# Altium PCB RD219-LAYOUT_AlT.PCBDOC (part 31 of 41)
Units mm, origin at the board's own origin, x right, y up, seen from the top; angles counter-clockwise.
Board outline 209.75 x 159.97 mm, 2 copper layers (TOP, BOTTOM), stack 0 mm thick; 398 components, 199 nets, 1469 pads, 0 vias.
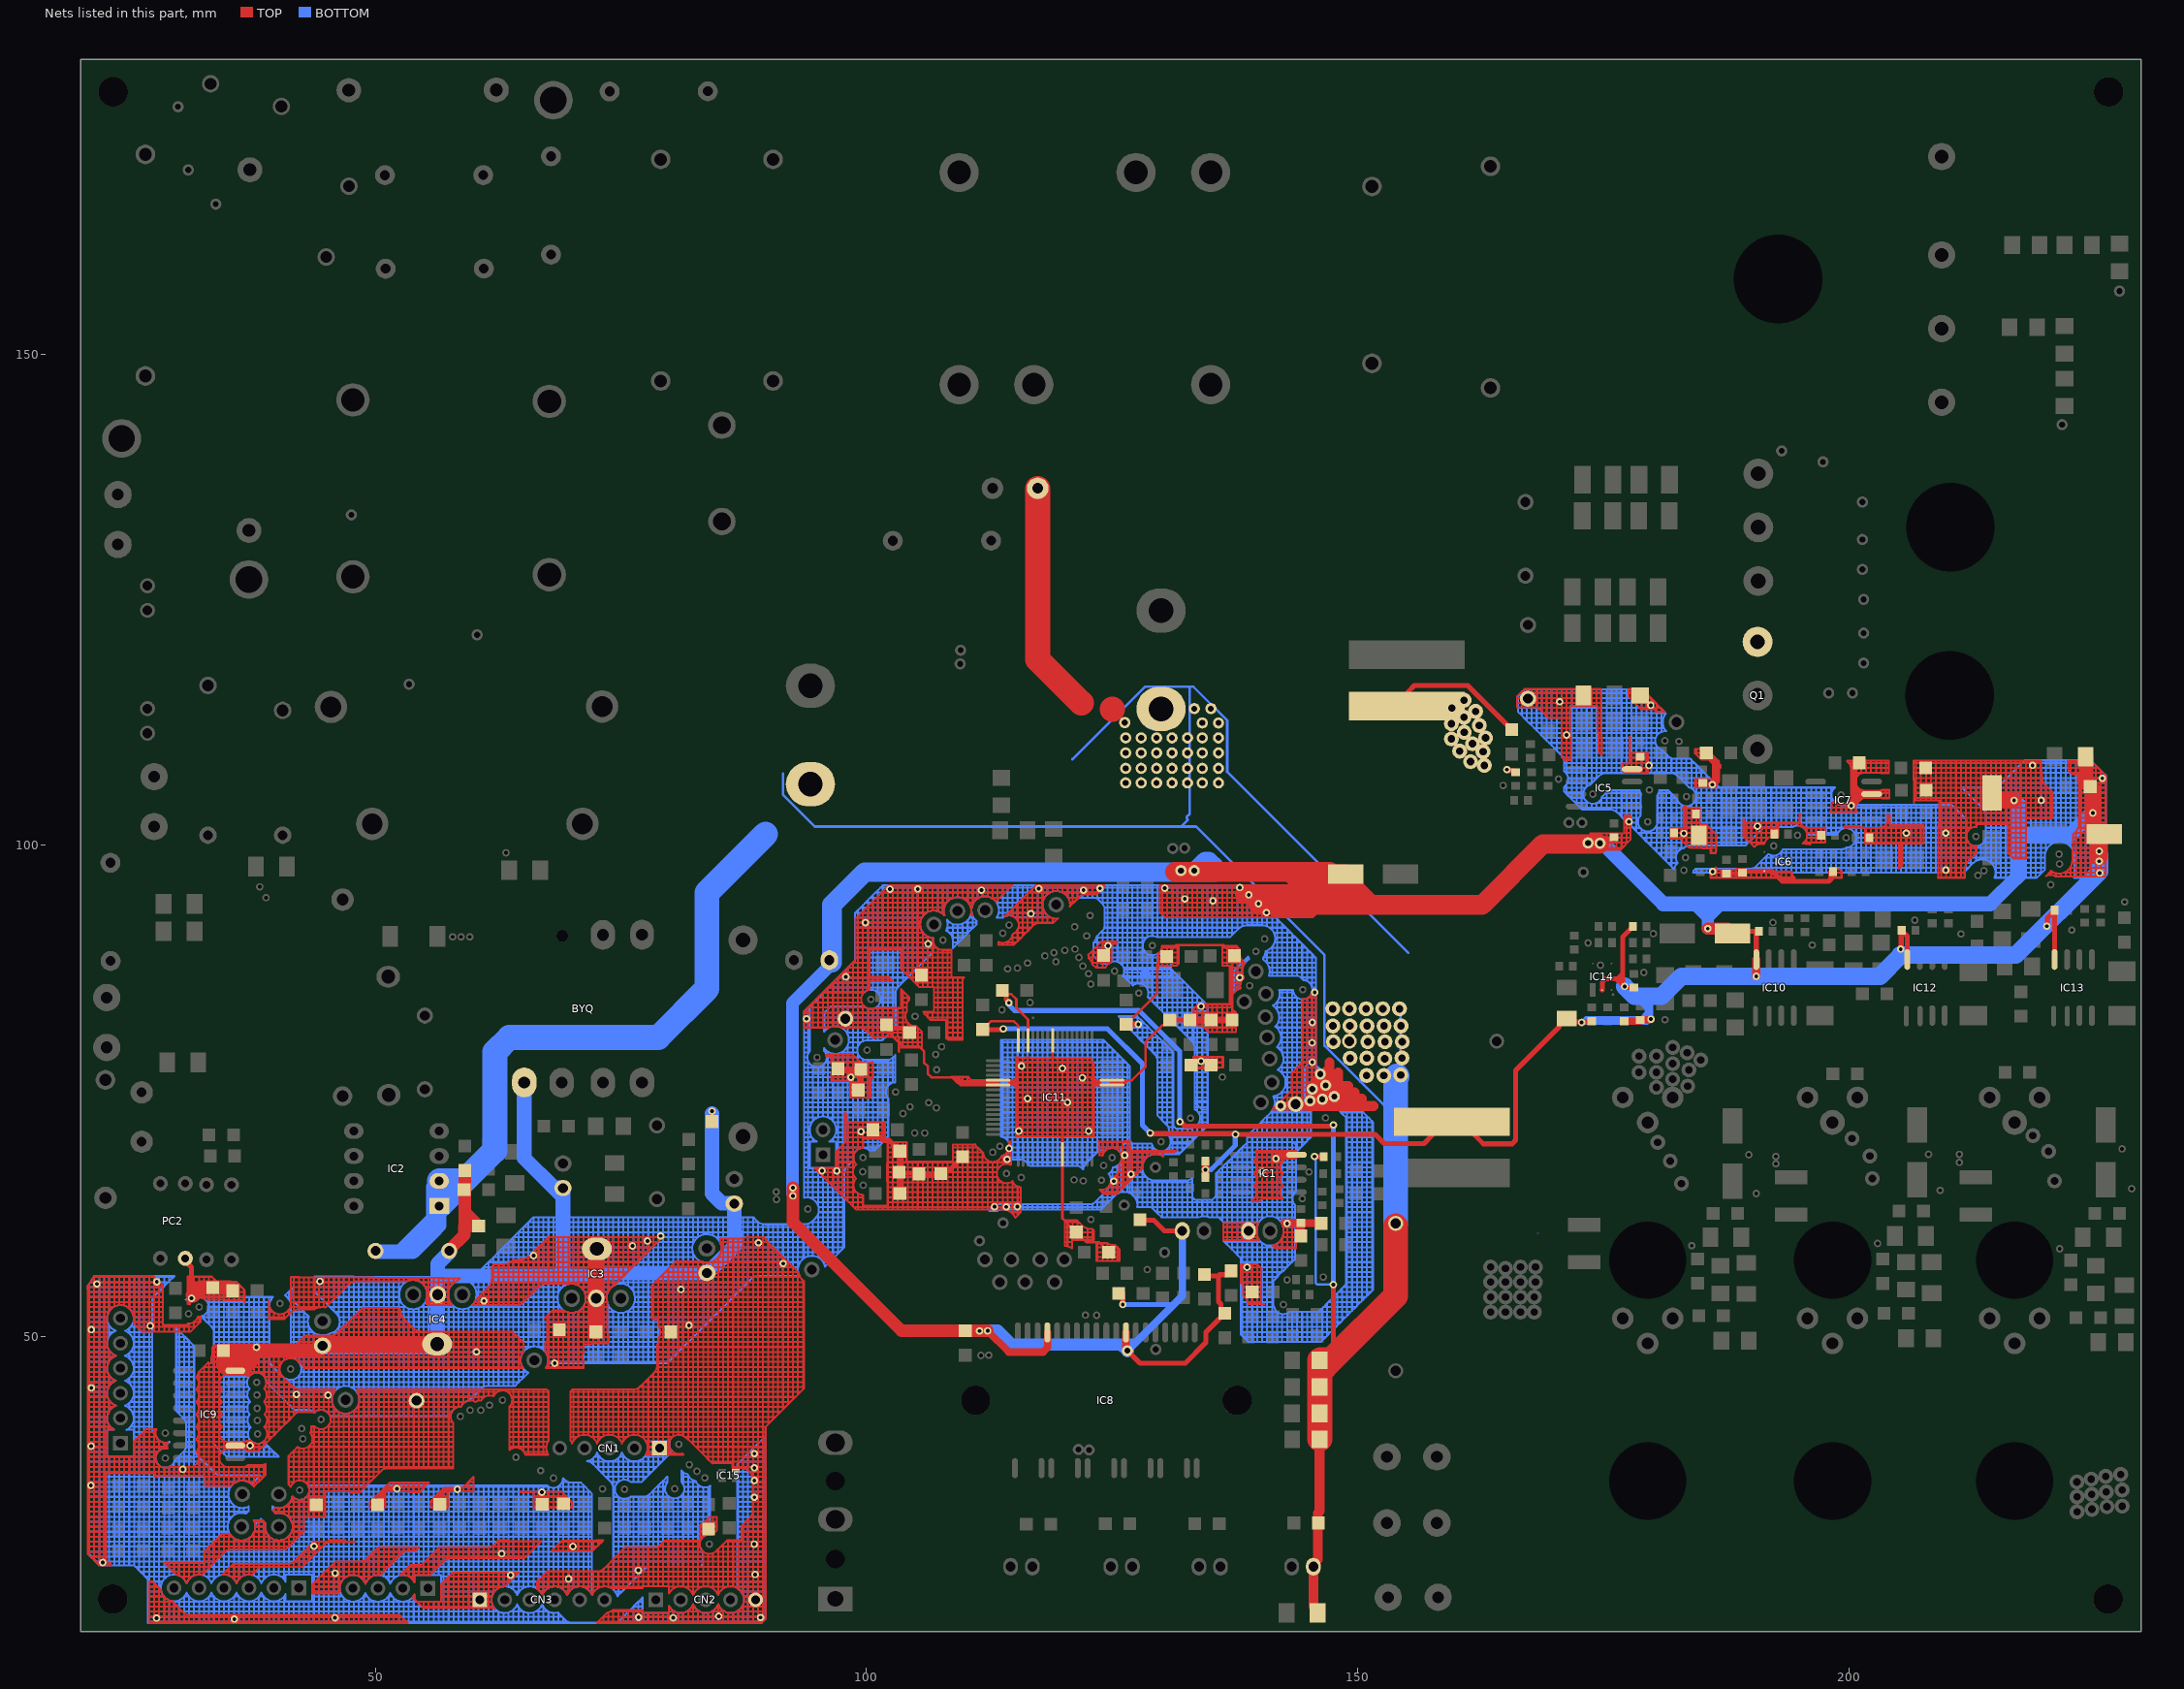
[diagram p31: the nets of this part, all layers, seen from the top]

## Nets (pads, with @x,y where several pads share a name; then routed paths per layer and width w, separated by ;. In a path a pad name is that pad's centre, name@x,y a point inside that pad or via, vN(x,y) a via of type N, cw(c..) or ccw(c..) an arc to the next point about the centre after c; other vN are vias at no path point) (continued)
GND: (continued)
  BOTTOM w0.203: 113.94,70.292 cw(c113.576,69.379) 114.361,69.971 ; 113.94,70.292 114.361,70.292 ; pad.@114.238,68.26 cw(c113.555,68.515) 114.097,68.027 ccw(c113.555,68.515) pad.@114.238,68.26 ; pad.@114.238,68.26 ccw(c113.555,68.515) 114.284,68.515 ; pad.@114.238,68.26 ccw(c113.555,68.515) 114.284,68.515 ; pad.@114.238,68.26 pad.@114.361,68.26 ; 114.284,68.515 114.284,68.698 ccw(c113.576,69.379) 114.346,68.768 ; 114.346,68.768 ccw(c113.576,69.379) 114.361,68.788 ; 114.346,68.768 114.361,68.768 ; pad.@114.361,62.944 114.869,62.944 ; pad.@114.361,62.944 pad.@114.361,63.18 ; pad.@114.361,63.18 114.869,63.18 ; pad.@114.361,63.18 pad.@114.361,63.467 ; pad.@114.361,63.467 114.869,63.467 ; pad.@114.361,68.025 114.869,68.025 ; pad.@114.361,68.025 pad.@114.361,68.26 ; pad.@114.361,68.26 114.869,68.26 ; pad.@114.361,68.26 114.361,68.768 ; 114.361,68.768 114.361,68.788 ; 114.361,68.768 114.869,68.768 ; 114.361,68.788 ccw(c113.576,69.379) pad.@114.553,69.276 ; 114.361,69.97 cw(c113.576,69.379) 114.472,69.784 ; 114.361,69.97 114.361,70.292 ; 114.361,70.292 114.361,70.8 ; 114.361,70.292 114.869,70.292 ; 114.361,70.8 114.361,71.308 ; 114.361,70.8 114.869,70.8 ; 114.361,71.308 114.361,71.816 ; 114.361,71.308 114.869,71.308 ; 114.361,71.816 114.361,72.324 ; 114.361,71.816 114.869,71.816 ; 114.361,72.324 114.361,72.832 ; 114.361,72.324 114.869,72.324 ; 114.361,72.832 114.361,73.34 ; 114.361,72.832 114.869,72.832 ; 114.361,73.34 114.361,73.848 ; 114.361,73.34 114.869,73.34 ; 114.361,73.848 114.361,74.356 ; 114.361,73.848 114.869,73.848 ; 114.361,74.356 114.361,74.864 ; 114.361,74.356 114.869,74.356 ; 114.361,74.864 114.361,75.372 ; 114.361,74.864 114.869,74.864 ; 114.361,75.372 114.361,75.88 ; 114.361,75.372 114.869,75.372 ; 114.361,75.88 114.361,76.388 ; 114.361,75.88 114.869,75.88 ; 114.361,76.388 114.361,76.896 ; 114.361,76.388 114.869,76.388 ; 114.361,76.896 114.361,77.404 ; 114.361,76.896 114.869,76.896 ; 114.361,77.404 114.361,77.912 ; 114.361,77.404 114.869,77.404 ; 114.361,77.912 114.361,78.42 ; 114.361,77.912 114.869,77.912 ; 114.361,78.42 114.361,78.928 ; 114.361,78.42 114.869,78.42 ; 114.361,78.928 114.361,79.436 ; 114.361,78.928 114.869,78.928 ; 114.361,79.436 114.361,79.944 ; 114.361,79.436 114.869,79.436 ; 114.361,79.944 114.361,80.198 ; 114.361,79.944 114.869,79.944 ; 114.361,80.198 114.869,80.198 ; 114.361,93.152 114.361,93.66 ; 114.361,93.152 114.869,93.152 ; 114.361,93.66 114.361,94.168 ; 114.361,93.66 114.869,93.66 ; 114.361,94.168 114.361,94.676 ; 114.361,94.168 114.869,94.168 ; 114.361,94.676 114.361,95.184 ; 114.361,94.676 114.869,94.676 ; 114.361,95.184 114.361,95.692 ; 114.361,95.184 114.869,95.184 ; 114.361,95.692 114.361,95.946 ; 114.361,95.692 114.869,95.692 ; 114.361,95.946 114.869,95.946 ; 114.472,69.784 cw(c113.576,69.379) 114.474,69.779 cw(c113.576,69.379) pad.@114.553,69.276 ; 114.472,69.784 114.869,69.784 ; pad.@114.553,69.276 pad.@114.869,69.276 ; 114.869,62.944 114.869,63.18 ; 114.869,62.944 pad.@115.377,62.944 ; 114.869,63.18 114.869,63.467 ; 114.869,63.18 pad.@115.377,63.18 ; 114.869,63.467 pad.@115.377,63.467 ; 114.869,68.025 114.869,68.26 ; 114.869,68.025 115.377,68.025 ; 114.869,68.26 114.869,68.768 ; 114.869,68.26 115.377,68.26 ; 114.869,68.768 115.377,68.768 ; 114.869,68.768 pad.@114.869,69.276 ; pad.@114.869,69.276 114.869,69.784 ; pad.@114.869,69.276 115.377,69.276 ; 114.869,69.784 114.869,70.292 ; 114.869,69.784 115.377,69.784 ; 114.869,70.292 114.869,70.8 ; 114.869,70.292 115.377,70.292 ; 114.869,70.8 114.869,71.308 ; 114.869,70.8 pad.@115.377,70.8 ; 114.869,71.308 114.869,71.816 ; 114.869,71.308 115.377,71.308 ; 114.869,71.816 114.869,72.324 ; 114.869,71.816 115.377,71.816 ; 114.869,72.324 114.869,72.832 ; 114.869,72.324 115.377,72.324 ; 114.869,72.832 114.869,73.34 ; 114.869,72.832 115.377,72.832 ; 114.869,73.34 114.869,73.848 ; 114.869,73.34 115.377,73.34 ; 114.869,73.848 114.869,74.356 ; 114.869,73.848 115.377,73.848 ; 114.869,74.356 114.869,74.864 ; 114.869,74.356 115.377,74.356 ; 114.869,74.864 114.869,75.372 ; 114.869,74.864 115.377,74.864 ; 114.869,75.372 114.869,75.88 ; 114.869,75.372 115.377,75.372 ; 114.869,75.88 114.869,76.388 ; 114.869,75.88 115.377,75.88 ; 114.869,76.388 114.869,76.896 ; 114.869,76.388 115.377,76.388 ; 114.869,76.896 114.869,77.404 ; 114.869,76.896 115.377,76.896 ; 114.869,77.404 114.869,77.912 ; 114.869,77.404 115.377,77.404 ; 114.869,77.912 114.869,78.42 ; 114.869,77.912 115.377,77.912 ; 114.869,78.42 114.869,78.928 ; 114.869,78.42 115.377,78.42 ; 114.869,78.928 114.869,79.436 ; 114.869,78.928 115.377,78.928 ; 114.869,79.436 114.869,79.944 ; 114.869,79.436 115.377,79.436 ; 114.869,79.944 114.869,80.198 ; 114.869,79.944 115.377,79.944 ; 114.869,80.198 115.377,80.198 ; 114.869,92.804 114.869,93.152 ; 114.869,93.152 114.869,93.66 ; 114.869,93.152 115.377,93.152 ; 114.869,93.66 114.869,94.168 ; 114.869,93.66 115.377,93.66 ; 114.869,94.168 114.869,94.676 ; 114.869,94.168 115.377,94.168 ; 114.869,94.676 114.869,95.184 ; 114.869,94.676 115.377,94.676 ; 114.869,95.184 114.869,95.692 ; 114.869,95.184 115.377,95.184 ; 114.869,95.692 114.869,95.946 ; 114.869,95.692 115.377,95.692 ; 114.869,95.946 115.377,95.946 ; pad.@115.377,62.944 pad.@115.377,63.18 ; pad.@115.377,62.944 115.885,62.944 ; pad.@115.377,63.18 115.885,63.18 ; pad.@115.377,63.18 pad.@115.377,63.467 ; pad.@115.377,63.467 115.885,63.467 ; 115.377,68.025 115.377,68.26 ; 115.377,68.025 115.706,68.025 ; 115.377,68.26 115.885,68.26 ; 115.377,68.26 115.377,68.768 ; 115.377,68.768 115.885,68.768 ; 115.377,68.768 115.377,69.276 ; 115.377,69.276 115.885,69.276 ; 115.377,69.276 115.377,69.784 ; 115.377,69.784 115.377,70.292 ; 115.377,69.784 115.885,69.784 ; 115.377,70.292 115.885,70.292 ; 115.377,70.292 pad.@115.377,70.8 ; pad.@115.377,70.8 115.885,70.8 ; pad.@115.377,70.8 115.377,71.308 ; 115.377,71.308 115.377,71.816 ; 115.377,71.308 115.885,71.308 ; 115.377,71.816 115.377,72.324 ; 115.377,71.816 115.885,71.816 ; 115.377,72.324 115.377,72.832 ; 115.377,72.324 115.885,72.324 ; 115.377,72.832 115.377,73.34 ; 115.377,72.832 115.885,72.832 ; 115.377,73.34 115.377,73.848 ; 115.377,73.34 115.885,73.34 ; 115.377,73.848 115.377,74.356 ; 115.377,73.848 115.885,73.848 ; 115.377,74.356 115.377,74.864 ; 115.377,74.356 115.885,74.356 ; 115.377,74.864 115.377,75.372 ; 115.377,74.864 115.885,74.864 ; 115.377,75.372 115.377,75.88 ; 115.377,75.372 115.885,75.372 ; 115.377,75.88 115.377,76.388 ; 115.377,75.88 115.885,75.88 ; 115.377,76.388 115.377,76.896 ; 115.377,76.388 115.885,76.388 ; 115.377,76.896 115.377,77.404 ; 115.377,76.896 115.885,76.896 ; 115.377,77.404 pad.@115.885,77.404 ; 115.377,77.404 115.377,77.912 ; 115.377,77.912 115.377,78.42 ; 115.377,77.912 pad.@115.885,77.912 ; 115.377,78.42 115.885,78.42 ; 115.377,78.42 115.377,78.928 ; 115.377,78.928 115.377,79.436 ; 115.377,78.928 115.885,78.928 ; 115.377,79.436 115.377,79.944 ; 115.377,79.436 115.885,79.436 ; 115.377,79.944 115.377,80.198 ; 115.377,79.944 115.885,79.944 ; 115.377,80.198 115.885,80.198 ; 115.377,92.692 115.377,93.152 ; 115.377,92.692 115.885,92.692 ; 115.377,93.152 115.377,93.66 ; 115.377,93.152 115.885,93.152 ; 115.377,93.66 115.377,94.168 ; 115.377,93.66 115.885,93.66 ; 115.377,94.168 115.377,94.676 ; 115.377,94.168 115.885,94.168 ; 115.377,94.676 115.377,95.184 ; 115.377,94.676 115.885,94.676 ; 115.377,95.184 115.377,95.692 ; 115.377,95.184 115.885,95.184 ; 115.377,95.692 115.377,95.946 ; 115.377,95.692 115.885,95.692 ; 115.377,95.946 115.885,95.946 ; 115.706,68.025 cw(c115.706,67.296) 115.885,68.002 ; 115.706,68.025 cw(c115.706,67.296) 115.885,68.002 ; 115.885,62.944 115.885,63.18 ; 115.885,62.944 116.393,62.944 ; 115.885,63.18 115.885,63.467 ; 115.885,63.18 116.393,63.18 ; 115.885,63.467 116.393,63.467 ; 115.885,68.002 cw(c115.706,67.296) 116.221,67.811 ; 115.885,68.002 cw(c115.706,67.296) 116.221,67.811 ; 115.885,68.002 115.885,68.26 ; 115.885,68.26 115.885,68.768 ; 115.885,68.26 116.393,68.26 ; 115.885,68.768 115.885,69.276 ; 115.885,68.768 116.393,68.768 ; 115.885,69.276 115.885,69.784 ; 115.885,69.276 116.393,69.276 ; 115.885,69.784 115.885,70.292 ; 115.885,69.784 116.393,69.784 ; 115.885,70.292 115.885,70.8 ; 115.885,70.292 116.393,70.292 ; 115.885,70.8 116.393,70.8 ; 115.885,70.8 115.885,71.308 ; 115.885,71.308 115.885,71.816 ; 115.885,71.308 116.393,71.308 ; 115.885,71.816 115.885,72.324 ; 115.885,71.816 116.393,71.816 ; 115.885,72.324 115.885,72.832 ; 115.885,72.324 116.393,72.324 ; 115.885,72.832 115.885,73.34 ; 115.885,72.832 116.393,72.832 ; 115.885,73.34 115.885,73.848 ; 115.885,73.34 116.393,73.34 ; 115.885,73.848 115.885,74.356 ; 115.885,73.848 116.393,73.848 ; 115.885,74.356 115.885,74.864 ; 115.885,74.356 pad.@116.393,74.356 ; 115.885,74.864 115.885,75.372 ; 115.885,74.864 116.393,74.864 ; 115.885,75.372 115.885,75.88 ; 115.885,75.372 116.393,75.372 ; 115.885,75.88 115.885,76.388 ; 115.885,75.88 116.393,75.88 ; 115.885,76.388 115.885,76.896 ; 115.885,76.388 116.393,76.388 ; 115.885,76.896 pad.@115.885,77.404 ; 115.885,76.896 116.393,76.896 ; pad.@115.885,77.404 116.393,77.404 ; pad.@115.885,77.404 pad.@115.885,77.912 ; pad.@115.885,77.912 116.393,77.912 ; pad.@115.885,77.912 115.885,78.42 ; 115.885,78.42 116.393,78.42 ; 115.885,78.42 115.885,78.928 ; 115.885,78.928 115.885,79.436 ; 115.885,78.928 116.393,78.928 ; 115.885,79.436 115.885,79.944 ; 115.885,79.436 116.393,79.436 ; 115.885,79.944 115.885,80.198 ; 115.885,79.944 116.393,79.944 ; 115.885,80.198 116.393,80.198 ; 115.885,92.692 115.885,93.152 ; 115.885,92.692 116.393,92.692 ; 115.885,93.152 115.885,93.66 ; 115.885,93.152 pad.@116.393,93.152 ; 115.885,93.66 115.885,94.168 ; 115.885,93.66 116.393,93.66 ; 115.885,94.168 115.885,94.676 ; 115.885,94.168 116.393,94.168 ; 115.885,94.676 115.885,95.184 ; 115.885,94.676 116.393,94.676 ; 115.885,95.184 115.885,95.692 ; 115.885,95.184 116.393,95.184 ; 115.885,95.692 115.885,95.946 ; 115.885,95.692 116.393,95.692 ; 115.885,95.946 116.393,95.946 ; 116.221,67.811 116.28,67.752 ; 116.28,67.752 116.393,67.639 ; 116.28,67.752 116.393,67.752 ; 116.393,62.944 116.393,63.18 ; 116.393,62.944 116.901,62.944 ; 116.393,63.18 116.393,63.467 ; 116.393,63.18 116.901,63.18 ; 116.393,63.467 116.901,63.467 ; 116.393,67.639 116.393,67.752 ; 116.393,67.639 116.653,67.379 116.901,67.379 ; 116.393,67.752 116.393,68.26 ; 116.393,67.752 116.901,67.752 ; 116.393,68.26 116.393,68.768 ; 116.393,68.26 116.901,68.26 ; 116.393,68.768 116.393,69.276 ; 116.393,68.768 116.901,68.768 ; 116.393,69.276 116.393,69.784 ; 116.393,69.276 116.901,69.276 ; 116.393,69.784 116.393,70.292 ; 116.393,69.784 116.901,69.784 ; 116.393,70.292 116.393,70.8 ; 116.393,70.292 116.901,70.292 ; 116.393,70.8 116.393,71.308 ; 116.393,70.8 116.901,70.8 ; 116.393,71.308 116.393,71.816 ; 116.393,71.308 116.901,71.308 ; 116.393,71.816 116.393,72.324 ; 116.393,71.816 116.901,71.816 ; 116.393,72.324 116.393,72.832 ; 116.393,72.324 116.901,72.324 ; 116.393,72.832 116.393,73.34 ; 116.393,72.832 116.901,72.832 ; 116.393,73.34 116.393,73.848 ; 116.393,73.34 116.901,73.34 ; 116.393,73.848 116.901,73.848 ; 116.393,73.848 pad.@116.393,74.356 ; pad.@116.393,74.356 116.393,74.864 ; pad.@116.393,74.356 116.901,74.356 ; 116.393,74.864 116.393,75.372 ; 116.393,74.864 116.901,74.864 ; 116.393,75.372 116.393,75.88 ; 116.393,75.372 116.901,75.372 ; 116.393,75.88 116.393,76.388 ; 116.393,75.88 116.901,75.88 ; 116.393,76.388 116.393,76.896 ; 116.393,76.388 116.901,76.388 ; 116.393,76.896 116.393,77.404 ; 116.393,76.896 116.901,76.896 ; 116.393,77.404 116.393,77.912 ; 116.393,77.404 116.901,77.404 ; 116.393,77.912 116.393,78.42 ; 116.393,77.912 116.901,77.912 ; 116.393,78.42 116.901,78.42 ; 116.393,78.42 116.393,78.928 ; 116.393,78.928 116.393,79.436 ; 116.393,78.928 116.901,78.928 ; 116.393,79.436 116.393,79.944 ; 116.393,79.436 116.901,79.436 ; 116.393,79.944 116.393,80.198 ; 116.393,79.944 116.901,79.944 ; 116.393,80.198 116.901,80.198 ; 116.393,92.692 116.901,92.692 ; 116.393,92.692 pad.@116.393,93.152 ; pad.@116.393,93.152 116.393,93.66 ; pad.@116.393,93.152 pad.@116.901,93.152 ; 116.393,93.66 116.393,94.168 ; 116.393,93.66 116.901,93.66 ; 116.393,94.168 116.393,94.676 ; 116.393,94.168 116.901,94.168 ; 116.393,94.676 116.393,95.184 ; 116.393,94.676 116.901,94.676 ; 116.393,95.184 116.393,95.692 ; 116.393,95.184 116.901,95.184 ; 116.393,95.692 116.393,95.946 ; 116.393,95.692 116.901,95.692 ; 116.393,95.946 116.901,95.946 ; 116.901,62.944 116.901,63.18 ; 116.901,62.944 117.409,62.944 ; 116.901,63.18 116.901,63.467 ; 116.901,63.18 117.409,63.18 ; 116.901,63.467 117.409,63.467 ; 116.901,67.379 116.901,67.752 ; 116.901,67.379 117.409,67.379 ; 116.901,67.752 116.901,68.26 ; 116.901,67.752 117.409,67.752 ; 116.901,68.26 116.901,68.768 ; 116.901,68.26 117.409,68.26 ; 116.901,68.768 116.901,69.276 ; 116.901,68.768 117.409,68.768 ; 116.901,69.276 116.901,69.784 ; 116.901,69.276 117.409,69.276 ; 116.901,69.784 116.901,70.292 ; 116.901,69.784 117.409,69.784 ; 116.901,70.292 116.901,70.8 ; 116.901,70.292 117.409,70.292 ; 116.901,70.8 116.901,71.308 ; 116.901,70.8 117.409,70.8 ; 116.901,71.308 116.901,71.816 ; 116.901,71.308 117.409,71.308 ; 116.901,71.816 116.901,72.324 ; 116.901,71.816 117.409,71.816 ; 116.901,72.324 116.901,72.832 ; 116.901,72.324 117.409,72.324 ; 116.901,72.832 116.901,73.34 ; 116.901,72.832 117.409,72.832 ; 116.901,73.34 116.901,73.848 ; 116.901,73.34 117.409,73.34 ; 116.901,73.848 116.901,74.356 ; 116.901,73.848 117.409,73.848 ; 116.901,74.356 116.901,74.864 ; 116.901,74.356 117.409,74.356 ; 116.901,74.864 116.901,75.372 ; 116.901,74.864 117.409,74.864 ; 116.901,75.372 116.901,75.88 ; 116.901,75.372 117.409,75.372 ; 116.901,75.88 116.901,76.388 ; 116.901,75.88 117.409,75.88 ; 116.901,76.388 116.901,76.896 ; 116.901,76.388 117.409,76.388 ; 116.901,76.896 116.901,77.404 ; 116.901,76.896 117.409,76.896 ; 116.901,77.404 116.901,77.912 ; 116.901,77.404 117.409,77.404 ; 116.901,77.912 116.901,78.42 ; 116.901,77.912 117.409,77.912 ; 116.901,78.42 116.901,78.928 ; 116.901,78.42 117.409,78.42 ; 116.901,78.928 116.901,79.436 ; 116.901,78.928 117.409,78.928 ; 116.901,79.436 116.901,79.944 ; 116.901,79.436 117.409,79.436 ; 116.901,79.944 116.901,80.198 ; 116.901,79.944 117.409,79.944 ; 116.901,80.198 117.409,80.198 ; 116.901,92.692 117.409,92.692 ; 116.901,92.692 pad.@116.901,93.152 ; pad.@116.901,93.152 116.901,93.66 ; pad.@116.901,93.152 117.409,93.152 ; 116.901,93.66 116.901,94.168 ; 116.901,93.66 117.409,93.66 ; 116.901,94.168 116.901,94.676 ; 116.901,94.168 117.409,94.168 ; 116.901,94.676 116.901,95.184 ; 116.901,94.676 117.409,94.676 ; 116.901,95.184 116.901,95.692 ; 116.901,95.184 117.409,95.184 ; 116.901,95.692 pad.@117.409,95.692 ; 116.901,95.692 116.901,95.946 ; 116.901,95.946 pad.@117.409,95.946 ; 117.409,62.944 117.409,63.18 ; 117.409,62.944 117.917,62.944 ; 117.409,63.18 117.409,63.467 ; 117.409,63.18 117.917,63.18 ; 117.409,63.467 117.917,63.467 ; 117.409,67.379 117.409,67.752 ; 117.409,67.379 117.917,67.379 ; 117.409,67.752 117.409,68.26 ; 117.409,67.752 117.917,67.752 ; 117.409,68.26 117.409,68.768 ; 117.409,68.26 117.917,68.26 ; 117.409,68.768 117.409,69.276 ; 117.409,68.768 117.917,68.768 ; 117.409,69.276 117.409,69.784 ; 117.409,69.276 117.917,69.276 ; 117.409,69.784 117.409,70.292 ; 117.409,69.784 117.917,69.784 ; 117.409,70.292 117.409,70.8 ; 117.409,70.292 117.917,70.292 ; 117.409,70.8 117.409,71.308 ; 117.409,70.8 117.917,70.8 ; 117.409,71.308 117.409,71.816 ; 117.409,71.308 117.917,71.308 ; 117.409,71.816 117.409,72.324 ; 117.409,71.816 117.917,71.816 ; 117.409,72.324 117.409,72.832 ; 117.409,72.324 117.917,72.324 ; 117.409,72.832 117.409,73.34 ; 117.409,72.832 117.917,72.832 ; 117.409,73.34 117.409,73.848 ; 117.409,73.34 117.917,73.34 ; 117.409,73.848 117.409,74.356 ; 117.409,73.848 117.917,73.848 ; 117.409,74.356 117.409,74.864 ; 117.409,74.356 117.917,74.356 ; 117.409,74.864 117.409,75.372 ; 117.409,74.864 117.917,74.864 ; 117.409,75.372 117.409,75.88 ; 117.409,75.372 117.917,75.372 ; 117.409,75.88 117.409,76.388 ; 117.409,75.88 117.917,75.88 ; 117.409,76.388 117.409,76.896 ; 117.409,76.388 117.917,76.388 ; 117.409,76.896 117.409,77.404 ; 117.409,76.896 117.917,76.896 ; 117.409,77.404 117.409,77.912 ; 117.409,77.404 117.917,77.404 ; 117.409,77.912 117.409,78.42 ; 117.409,77.912 117.917,77.912 ; 117.409,78.42 117.409,78.928 ; 117.409,78.42 117.917,78.42 ; 117.409,78.928 117.409,79.436 ; 117.409,78.928 117.917,78.928 ; 117.409,79.436 117.409,79.944 ; 117.409,79.436 117.917,79.436 ; 117.409,79.944 117.409,80.198 ; 117.409,79.944 117.917,79.944 ; 117.409,80.198 117.917,80.198 ; 117.409,92.692 117.917,92.692 ; 117.409,92.692 117.409,93.152 ; 117.409,93.152 117.409,93.66 ; 117.409,93.152 117.917,93.152 ; 117.409,93.66 117.917,93.66 ; 117.409,93.66 117.409,94.168 ; 117.409,94.168 117.917,94.168 ; 117.409,94.168 117.409,94.676 ; 117.409,94.676 117.409,95.184 ; 117.409,94.676 117.917,94.676 ; 117.409,95.184 117.917,95.184 ; 117.409,95.184 pad.@117.409,95.692 ; pad.@117.409,95.692 pad.@117.409,95.946 ; pad.@117.409,95.692 117.917,95.692 ; pad.@117.409,95.946 117.917,95.946 ; 117.917,62.944 117.917,63.18 ; 117.917,62.944 118.425,62.944 ; 117.917,63.18 117.917,63.467 ; 117.917,63.18 118.425,63.18 ; 117.917,63.467 118.425,63.467 ; 117.917,67.379 117.917,67.752 ; 117.917,67.379 118.425,67.379 ; 117.917,67.752 117.917,68.26 ; 117.917,67.752 118.425,67.752 ; 117.917,68.26 117.917,68.768 ; 117.917,68.26 118.425,68.26 ; 117.917,68.768 117.917,69.276 ; 117.917,68.768 118.425,68.768 ; 117.917,69.276 117.917,69.784 ; 117.917,69.276 118.425,69.276 ; 117.917,69.784 117.917,70.292 ; 117.917,69.784 118.425,69.784 ; 117.917,70.292 117.917,70.8 ; 117.917,70.292 118.425,70.292 ; 117.917,70.8 117.917,71.308 ; 117.917,70.8 118.425,70.8 ; 117.917,71.308 117.917,71.816 ; 117.917,71.308 118.425,71.308 ; 117.917,71.816 117.917,72.324 ; 117.917,71.816 118.425,71.816 ; 117.917,72.324 117.917,72.832 ; 117.917,72.324 118.425,72.324 ; 117.917,72.832 117.917,73.34 ; 117.917,72.832 118.425,72.832 ; 117.917,73.34 117.917,73.848 ; 117.917,73.34 118.425,73.34 ; 117.917,73.848 117.917,74.356 ; 117.917,73.848 118.425,73.848 ; 117.917,74.356 117.917,74.864 ; 117.917,74.356 118.425,74.356 ; 117.917,74.864 117.917,75.372 ; 117.917,74.864 118.425,74.864 ; 117.917,75.372 117.917,75.88 ; 117.917,75.372 118.425,75.372 ; 117.917,75.88 117.917,76.388 ; 117.917,75.88 118.425,75.88 ; 117.917,76.388 117.917,76.896 ; 117.917,76.388 118.425,76.388 ; 117.917,76.896 117.917,77.404 ; 117.917,76.896 118.425,76.896 ; 117.917,77.404 117.917,77.912 ; 117.917,77.404 118.425,77.404 ; 117.917,77.912 117.917,78.42 ; 117.917,77.912 118.425,77.912 ; 117.917,78.42 117.917,78.928 ; 117.917,78.42 118.425,78.42 ; 117.917,78.928 117.917,79.436 ; 117.917,78.928 118.425,78.928 ; 117.917,79.436 117.917,79.944 ; 117.917,79.436 118.425,79.436 ; 117.917,79.944 117.917,80.198 ; 117.917,79.944 118.425,79.944 ; 117.917,80.198 118.425,80.198 ; 117.917,92.692 117.917,93.152 ; 117.917,92.692 118.425,92.692 ; 117.917,93.152 117.917,93.66 ; 117.917,93.152 118.165,93.152 ; 117.917,93.66 117.944,93.66 ; 117.917,94.067 cw(c119.314,93.954) 117.918,94.076 cw(c119.314,93.954) 117.929,94.168 ; 117.917,94.067 117.917,94.168 ; 117.917,94.168 117.917,94.676 ; 117.917,94.168 117.929,94.168 ; 117.917,94.676 117.917,95.184 ; 117.917,94.676 118.113,94.676 ; 117.917,95.184 118.425,95.184 ; 117.917,95.184 117.917,95.692 ; 117.917,95.692 117.917,95.946 ; 117.917,95.692 118.425,95.692 ; 117.917,95.946 118.425,95.946 ; 117.929,94.168 cw(c119.314,93.954) 118.113,94.676 ; 117.944,93.66 ccw(c119.314,93.954) 118.165,93.152 ; 118.113,94.676 cw(c119.314,93.954) 118.425,95.038 ; 118.165,93.152 ccw(c119.314,93.954) 118.166,93.15 ccw(c119.314,93.954) 118.425,92.87 ; 118.425,62.944 118.425,63.18 ; 118.425,62.944 118.933,62.944 ; 118.425,63.18 118.425,63.467 ; 118.425,63.18 118.933,63.18 ; 118.425,63.467 118.933,63.467 ; 118.425,67.379 118.425,67.752 ; 118.425,67.379 118.933,67.379 ; 118.425,67.752 118.425,68.26 ; 118.425,67.752 118.933,67.752 ; 118.425,68.26 118.425,68.768 ; 118.425,68.26 118.933,68.26 ; 118.425,68.768 118.425,69.276 ; 118.425,68.768 118.933,68.768 ; 118.425,69.276 118.425,69.784 ; 118.425,69.276 118.933,69.276 ; 118.425,69.784 118.425,70.292 ; 118.425,69.784 118.933,69.784 ; 118.425,70.292 118.425,70.8 ; 118.425,70.292 118.933,70.292 ; 118.425,70.8 118.425,71.308 ; 118.425,70.8 118.933,70.8 ; 118.425,71.308 118.425,71.816 ; 118.425,71.308 118.933,71.308 ; 118.425,71.816 118.425,72.324 ; 118.425,71.816 118.933,71.816 ; 118.425,72.324 118.425,72.832 ; 118.425,72.324 118.933,72.324 ; 118.425,72.832 118.425,73.34 ; 118.425,72.832 118.933,72.832 ; 118.425,73.34 118.425,73.848 ; 118.425,73.34 118.933,73.34 ; 118.425,73.848 118.425,74.356 ; 118.425,73.848 118.933,73.848 ; 118.425,74.356 118.425,74.864 ; 118.425,74.356 118.933,74.356 ; 118.425,74.864 118.425,75.372 ; 118.425,74.864 118.933,74.864 ; 118.425,75.372 118.425,75.88 ; 118.425,75.372 118.933,75.372 ; 118.425,75.88 118.425,76.388 ; 118.425,75.88 118.933,75.88 ; 118.425,76.388 118.425,76.896 ; 118.425,76.388 118.933,76.388 ; 118.425,76.896 118.425,77.404 ; 118.425,76.896 118.933,76.896 ; 118.425,77.404 118.425,77.912 ; 118.425,77.404 118.933,77.404 ; 118.425,77.912 118.425,78.42 ; 118.425,77.912 118.933,77.912 ; 118.425,78.42 118.425,78.928 ; 118.425,78.42 118.933,78.42 ; 118.425,78.928 118.425,79.436 ; 118.425,78.928 118.933,78.928 ; 118.425,79.436 118.425,79.944 ; 118.425,79.436 118.933,79.436 ; 118.425,79.944 118.425,80.198 ; 118.425,79.944 118.933,79.944 ; 118.425,80.198 118.933,80.198 ; 118.425,92.692 118.425,92.87 ; 118.425,92.692 118.704,92.692 ; 118.425,92.87 ccw(c119.314,93.954) 118.432,92.865 ccw(c119.314,93.954) 118.704,92.692 ; 118.425,95.038 cw(c119.314,93.954) 118.635,95.18 cw(c119.314,93.954) 118.642,95.184 ; 118.425,95.038 118.425,95.184 ; 118.425,95.184 118.425,95.692 ; 118.425,95.184 118.642,95.184 ; 118.425,95.692 118.425,95.946 ; 118.425,95.692 118.933,95.692 ; 118.425,95.946 118.933,95.946 ; 118.642,95.184 cw(c119.314,93.954) 118.928,95.301 cw(c119.314,93.954) 118.933,95.303 ; 118.933,62.944 118.933,63.18 ; 118.933,62.944 119.441,62.944 ; 118.933,63.18 118.933,63.467 ; 118.933,63.18 119.441,63.18 ; 118.933,63.467 119.441,63.467 ; 118.933,67.379 118.933,67.752 ; 118.933,67.379 119.441,67.379 ; 118.933,67.752 118.933,68.26 ; 118.933,67.752 119.441,67.752 ; 118.933,68.26 118.933,68.768 ; 118.933,68.26 119.441,68.26 ; 118.933,68.768 118.933,69.276 ; 118.933,68.768 119.441,68.768 ; 118.933,69.276 118.933,69.784 ; 118.933,69.276 119.441,69.276 ; 118.933,69.784 118.933,70.292 ; 118.933,69.784 119.441,69.784 ; 118.933,70.292 118.933,70.8 ; 118.933,70.292 119.441,70.292 ; 118.933,70.8 118.933,71.308 ; 118.933,70.8 119.441,70.8 ; 118.933,71.308 118.933,71.816 ; 118.933,71.308 119.441,71.308 ; 118.933,71.816 118.933,72.324 ; 118.933,71.816 119.441,71.816 ; 118.933,72.324 118.933,72.832 ; 118.933,72.324 119.441,72.324 ; 118.933,72.832 118.933,73.34 ; 118.933,72.832 119.441,72.832 ; 118.933,73.34 118.933,73.848 ; 118.933,73.34 119.441,73.34 ; 118.933,73.848 118.933,74.356 ; 118.933,73.848 119.441,73.848 ; 118.933,74.356 118.933,74.864 ; 118.933,74.356 119.441,74.356 ; 118.933,74.864 118.933,75.372 ; 118.933,74.864 119.441,74.864 ; 118.933,75.372 118.933,75.88 ; 118.933,75.372 119.441,75.372 ; 118.933,75.88 118.933,76.388 ; 118.933,75.88 119.441,75.88 ; 118.933,76.388 118.933,76.896 ; 118.933,76.388 119.441,76.388 ; 118.933,76.896 118.933,77.404 ; 118.933,76.896 119.441,76.896 ; 118.933,77.404 118.933,77.912 ; 118.933,77.404 119.441,77.404 ; 118.933,77.912 118.933,78.42 ; 118.933,77.912 119.441,77.912 ; 118.933,78.42 118.933,78.928 ; 118.933,78.42 119.441,78.42 ; 118.933,78.928 118.933,79.436 ; 118.933,78.928 119.441,78.928 ; 118.933,79.436 118.933,79.944 ; 118.933,79.436 119.441,79.436 ; 118.933,79.944 118.933,80.198 ; 118.933,79.944 119.441,79.944 ; 118.933,80.198 119.441,80.198 ; 118.933,95.303 118.933,95.692 ; 118.933,95.692 118.933,95.946 ; 118.933,95.692 119.441,95.692 ; 118.933,95.946 119.441,95.946 ; 119.441,62.944 119.441,63.18 ; 119.441,62.944 119.949,62.944 ; 119.441,63.18 119.441,63.467 ; 119.441,63.18 119.949,63.18 ; 119.441,63.467 119.949,63.467 ; 119.441,67.379 119.441,67.752 ; 119.441,67.379 119.949,67.379 ; 119.441,67.752 119.441,68.26 ; 119.441,67.752 119.949,67.752 ; 119.441,68.26 119.441,68.768 ; 119.441,68.26 119.949,68.26 ; 119.441,68.768 119.441,69.276 ; 119.441,68.768 119.949,68.768 ; 119.441,69.276 119.441,69.784 ; 119.441,69.276 119.949,69.276 ; 119.441,69.784 119.441,70.292 ; 119.441,69.784 119.949,69.784 ; 119.441,70.292 119.441,70.8 ; 119.441,70.292 119.949,70.292 ; 119.441,70.8 119.441,71.308 ; 119.441,70.8 119.949,70.8 ; 119.441,71.308 119.441,71.816 ; 119.441,71.308 119.949,71.308 ; 119.441,71.816 119.441,72.324 ; 119.441,71.816 119.949,71.816 ; 119.441,72.324 119.441,72.832 ; 119.441,72.324 119.949,72.324 ; 119.441,72.832 119.441,73.34 ; 119.441,72.832 119.949,72.832 ; 119.441,73.34 119.441,73.848 ; 119.441,73.34 119.949,73.34 ; 119.441,73.848 119.441,74.356 ; 119.441,73.848 119.949,73.848 ; 119.441,74.356 119.441,74.864 ; 119.441,74.356 119.949,74.356 ; 119.441,74.864 119.441,75.372 ; 119.441,74.864 119.949,74.864 ; 119.441,75.372 119.441,75.88 ; 119.441,75.372 119.949,75.372 ; 119.441,75.88 119.441,76.388 ; 119.441,75.88 119.949,75.88 ; 119.441,76.388 119.441,76.896 ; 119.441,76.388 119.949,76.388 ; 119.441,76.896 119.441,77.404 ; 119.441,76.896 119.949,76.896 ; 119.441,77.404 119.441,77.912 ; 119.441,77.404 pad.@119.949,77.404 ; 119.441,77.912 119.441,78.42 ; 119.441,77.912 119.949,77.912 ; 119.441,78.42 119.441,78.928 ; 119.441,78.42 119.949,78.42 ; 119.441,78.928 119.441,79.436 ; 119.441,78.928 119.949,78.928 ; 119.441,79.436 119.441,79.944 ; 119.441,79.436 119.949,79.436 ; 119.441,79.944 119.441,80.198 ; 119.441,79.944 119.949,79.944 ; 119.441,80.198 119.949,80.198 ; 119.441,95.692 119.949,95.692 ; 119.441,95.692 119.441,95.946 ; 119.441,95.946 119.949,95.946 ; 119.949,62.944 119.949,63.18 ; 119.949,62.944 120.457,62.944 ; 119.949,63.18 119.949,63.467 ; 119.949,63.18 120.457,63.18 ; 119.949,63.467 120.457,63.467 ; 119.949,67.379 119.949,67.752 ; 119.949,67.379 120.457,67.379 ; 119.949,67.752 119.949,68.26 ; 119.949,67.752 120.457,67.752 ; 119.949,68.26 119.949,68.768 ; 119.949,68.26 120.457,68.26 ; 119.949,68.768 119.949,69.276 ; 119.949,68.768 120.457,68.768 ; 119.949,69.276 119.949,69.784 ; 119.949,69.276 120.457,69.276 ; 119.949,69.784 119.949,70.292 ; 119.949,69.784 120.457,69.784 ; 119.949,70.292 119.949,70.8 ; 119.949,70.292 120.457,70.292 ; 119.949,70.8 119.949,71.308 ; 119.949,70.8 120.457,70.8 ; 119.949,71.308 119.949,71.816 ; 119.949,71.308 120.457,71.308 ; 119.949,71.816 119.949,72.324 ; 119.949,71.816 120.457,71.816 ; 119.949,72.324 119.949,72.832 ; 119.949,72.324 120.457,72.324 ; 119.949,72.832 119.949,73.34 ; 119.949,72.832 120.457,72.832 ; 119.949,73.34 119.949,73.848 ; 119.949,73.34 120.457,73.34 ; 119.949,73.848 119.949,74.356 ; 119.949,73.848 pad.@120.457,73.848 ; 119.949,74.356 119.949,74.864 ; 119.949,74.356 120.457,74.356 ; 119.949,74.864 119.949,75.372 ; 119.949,74.864 120.457,74.864 ; 119.949,75.372 119.949,75.88 ; 119.949,75.372 120.457,75.372 ; 119.949,75.88 119.949,76.388 ; 119.949,75.88 120.457,75.88 ; 119.949,76.388 119.949,76.896 ; 119.949,76.388 120.457,76.388 ; 119.949,76.896 120.457,76.896 ; 119.949,76.896 pad.@119.949,77.404 ; pad.@119.949,77.404 119.949,77.912 ; pad.@119.949,77.404 120.457,77.404 ; 119.949,77.912 119.949,78.42 ; 119.949,77.912 120.457,77.912 ; 119.949,78.42 119.949,78.928 ; 119.949,78.42 120.457,78.42 ; 119.949,78.928 119.949,79.436 ; 119.949,78.928 120.457,78.928 ; 119.949,79.436 119.949,79.944 ; 119.949,79.436 120.457,79.436 ; 119.949,79.944 119.949,80.198 ; 119.949,79.944 120.457,79.944 ; 119.949,80.198 120.457,80.198 ; 119.949,95.204 cw(c119.314,93.954) 119.986,95.184 ; 119.949,95.204 119.949,95.692 ; 119.949,95.692 120.457,95.692 ; 119.949,95.692 119.949,95.946 ; 119.949,95.946 120.457,95.946 ; 119.986,95.184 cw(c119.314,93.954) 120.457,94.765 ; 119.986,95.184 120.457,95.184 ; 120.457,62.944 120.457,63.18 ; 120.457,62.944 120.965,62.944 ; 120.457,63.18 120.457,63.467 ; 120.457,63.18 120.965,63.18 ; 120.457,63.467 120.965,63.467 ; 120.457,67.379 120.457,67.752 ; 120.457,67.379 120.965,67.379 ; 120.457,67.752 120.457,68.26 ; 120.457,67.752 120.965,67.752 ; 120.457,68.26 120.457,68.768 ; 120.457,68.26 120.965,68.26 ; 120.457,68.768 120.457,69.276 ; 120.457,68.768 120.965,68.768 ; 120.457,69.276 120.457,69.784 ; 120.457,69.276 120.965,69.276 ; 120.457,69.784 120.457,70.292 ; 120.457,69.784 120.965,69.784 ; 120.457,70.292 120.457,70.8 ; 120.457,70.292 120.965,70.292 ; 120.457,70.8 120.457,71.308 ; 120.457,70.8 120.965,70.8 ; 120.457,71.308 120.457,71.816 ; 120.457,71.308 120.965,71.308 ; 120.457,71.816 120.457,72.324 ; 120.457,71.816 120.965,71.816 ; 120.457,72.324 120.457,72.832 ; 120.457,72.324 120.965,72.324 ; 120.457,72.832 120.457,73.34 ; 120.457,72.832 120.965,72.832 ; 120.457,73.34 pad.@120.457,73.848 ; 120.457,73.34 120.965,73.34 ; pad.@120.457,73.848 120.457,74.356 ; pad.@120.457,73.848 120.965,73.848 ; 120.457,74.356 120.457,74.864 ; 120.457,74.356 120.965,74.356 ; 120.457,74.864 120.457,75.372 ; 120.457,74.864 120.965,74.864 ; 120.457,75.372 120.457,75.88 ; 120.457,75.372 120.965,75.372 ; 120.457,75.88 120.457,76.388 ; 120.457,75.88 120.965,75.88 ; 120.457,76.388 120.457,76.896 ; 120.457,76.388 120.965,76.388 ; 120.457,76.896 120.457,77.404 ; 120.457,76.896 120.965,76.896 ; 120.457,77.404 120.457,77.912 ; 120.457,77.404 120.965,77.404 ; 120.457,77.912 120.457,78.42 ; 120.457,77.912 120.965,77.912 ; 120.457,78.42 120.457,78.928 ; 120.457,78.42 120.965,78.42 ; 120.457,78.928 120.457,79.436 ; 120.457,78.928 120.965,78.928 ; 120.457,79.436 120.457,79.944 ; 120.457,79.436 120.965,79.436 ; 120.457,79.944 120.457,80.198 ; 120.457,79.944 120.965,79.944 ; 120.457,80.198 120.965,80.198 ; 120.457,94.765 cw(c119.314,93.954) 120.511,94.683 ; 120.457,94.765 120.457,95.184 ; 120.457,95.184 120.457,95.692 ; 120.457,95.184 120.965,95.184 ; 120.457,95.692 120.965,95.692 ; 120.457,95.692 120.457,95.946 ; 120.457,95.946 120.965,95.946 ; 120.511,94.683 120.965,94.683 ; 120.965,62.944 120.965,63.18 ; 120.965,62.944 121.473,62.944 ; 120.965,63.18 120.965,63.467 ; 120.965,63.18 121.473,63.18 ; 120.965,63.467 121.473,63.467 ; 120.965,67.379 120.965,67.752 ; 120.965,67.379 121.407,67.379 ; 120.965,67.752 121.473,67.752 ; 120.965,67.752 120.965,68.26 ; 120.965,68.26 121.473,68.26 ; 120.965,68.26 120.965,68.768 ; 120.965,68.768 121.473,68.768 ; 120.965,68.768 120.965,69.276 ; 120.965,69.276 121.473,69.276 ; 120.965,69.276 120.965,69.784 ; 120.965,69.784 120.965,70.292 ; 120.965,69.784 121.473,69.784 ; 120.965,70.292 121.473,70.292 ; 120.965,70.292 120.965,70.8 ; 120.965,70.8 120.965,71.308 ; 120.965,70.8 121.473,70.8 ; 120.965,71.308 120.965,71.816 ; 120.965,71.308 121.473,71.308 ; 120.965,71.816 120.965,72.324 ; 120.965,71.816 121.473,71.816 ; 120.965,72.324 120.965,72.832 ; 120.965,72.324 121.473,72.324 ; 120.965,72.832 120.965,73.34 ; 120.965,72.832 121.473,72.832 ; 120.965,73.34 120.965,73.848 ; 120.965,73.34 121.473,73.34 ; 120.965,73.848 120.965,74.356 ; 120.965,73.848 121.473,73.848 ; 120.965,74.356 120.965,74.864 ; 120.965,74.356 121.473,74.356 ; 120.965,74.864 120.965,75.372 ; 120.965,74.864 121.473,74.864 ; 120.965,75.372 120.965,75.88 ; 120.965,75.372 121.473,75.372 ; 120.965,75.88 120.965,76.388 ; 120.965,75.88 121.473,75.88 ; 120.965,76.388 120.965,76.896 ; 120.965,76.388 121.473,76.388 ; 120.965,76.896 120.965,77.404 ; 120.965,76.896 121.473,76.896 ; 120.965,77.404 121.473,77.404 ; 120.965,77.404 120.965,77.912 ; 120.965,77.912 121.473,77.912 ; 120.965,77.912 120.965,78.42 ; 120.965,78.42 121.473,78.42 ; 120.965,78.42 120.965,78.928 ; 120.965,78.928 120.965,79.436 ; 120.965,78.928 121.473,78.928 ; 120.965,79.436 120.965,79.944 ; 120.965,79.436 121.473,79.436 ; 120.965,79.944 120.965,80.198 ; 120.965,79.944 121.473,79.944 ; 120.965,80.198 121.473,80.198 ; 120.965,94.683 120.965,95.184 ; 120.965,94.683 121.473,94.683 ; 120.965,95.184 120.965,95.692 ; 120.965,95.184 121.473,95.184 ; 120.965,95.692 120.965,95.946 ; 120.965,95.692 121.473,95.692 ; 120.965,95.946 121.473,95.946 ; 121.407,67.379 cw(c121.407,66.65) 121.473,67.376 ; 121.407,67.379 cw(c121.407,66.65) 121.473,67.376 ; 121.473,62.944 121.473,63.18 ; 121.473,62.944 121.981,62.944 ; 121.473,63.18 121.473,63.467 ; 121.473,63.18 121.981,63.18 ; 121.473,63.467 121.981,63.467 ; 121.473,67.376 cw(c121.407,66.65) 121.83,67.244 ; 121.473,67.376 cw(c121.407,66.65) 121.83,67.244 ; 121.473,67.376 121.473,67.752 ; 121.473,67.752 121.473,68.26 ; 121.473,67.752 121.981,67.752 ; 121.473,68.26 121.473,68.768 ; 121.473,68.26 121.981,68.26 ; 121.473,68.768 121.473,69.276 ; 121.473,68.768 121.981,68.768 ; 121.473,69.276 121.981,69.276 ; 121.473,69.276 121.473,69.784 ; 121.473,69.784 121.473,70.292 ; 121.473,69.784 121.981,69.784 ; 121.473,70.292 121.981,70.292 ; 121.473,70.292 121.473,70.8 ; 121.473,70.8 121.473,71.308 ; 121.473,70.8 121.981,70.8 ; 121.473,71.308 121.473,71.816 ; 121.473,71.308 121.981,71.308 ; 121.473,71.816 121.473,72.324 ; 121.473,71.816 121.981,71.816 ; 121.473,72.324 121.473,72.832 ; 121.473,72.324 121.981,72.324 ; 121.473,72.832 121.473,73.34 ; 121.473,72.832 121.981,72.832 ; 121.473,73.34 121.473,73.848 ; 121.473,73.34 121.981,73.34 ; 121.473,73.848 121.473,74.356 ; 121.473,73.848 121.981,73.848 ; 121.473,74.356 121.473,74.864 ; 121.473,74.356 121.981,74.356 ; 121.473,74.864 121.473,75.372 ; 121.473,74.864 121.981,74.864 ; 121.473,75.372 121.473,75.88 ; 121.473,75.372 121.981,75.372 ; 121.473,75.88 121.473,76.388 ; 121.473,75.88 121.981,75.88 ; 121.473,76.388 121.473,76.896 ; 121.473,76.388 pad.@121.981,76.388 ; 121.473,76.896 121.473,77.404 ; 121.473,76.896 121.981,76.896 ; 121.473,77.404 121.981,77.404 ; 121.473,77.404 121.473,77.912 ; 121.473,77.912 121.981,77.912 ; 121.473,77.912 121.473,78.42 ; 121.473,78.42 121.981,78.42 ; 121.473,78.42 121.473,78.928 ; 121.473,78.928 121.473,79.436 ; 121.473,78.928 121.981,78.928 ; 121.473,79.436 121.473,79.944 ; 121.473,79.436 121.981,79.436 ; 121.473,79.944 121.473,80.198 ; 121.473,79.944 121.981,79.944 ; 121.473,80.198 121.981,80.198 ; 121.473,94.683 121.473,95.184 ; 121.473,94.683 121.981,94.683 ; 121.473,95.184 121.473,95.692 ; 121.473,95.184 pad.@121.981,95.184 ; 121.473,95.692 121.473,95.946 ; 121.473,95.692 pad.@121.981,95.692 ; 121.473,95.946 121.981,95.946 ; 121.83,67.244 cw(c121.407,66.65) 121.922,67.166 ; 121.83,67.244 cw(c121.407,66.65) 121.922,67.166 ; 121.83,67.244 121.981,67.244 ; 121.981,62.944 121.981,63.18 ; 121.981,62.944 122.489,62.944 ; 121.981,63.18 121.981,63.467 ; 121.981,63.18 122.489,63.18 ; 121.981,63.467 122.489,63.467 ; 121.981,67.244 121.981,67.752 ; 121.981,67.244 122.094,67.244 ; 121.981,67.752 121.981,68.26 ; 121.981,67.752 122.475,67.752 ; 121.981,68.26 121.981,68.768 ; 121.981,68.26 122.489,68.26 ; 121.981,68.768 121.981,69.276 ; 121.981,68.768 122.489,68.768 ; 121.981,69.276 122.489,69.276 ; 121.981,69.276 121.981,69.784 ; 121.981,69.784 121.981,70.292 ; 121.981,69.784 122.489,69.784 ; 121.981,70.292 122.489,70.292 ; 121.981,70.292 121.981,70.8 ; 121.981,70.8 121.981,71.308 ; 121.981,70.8 pad.@122.489,70.8 ; 121.981,71.308 121.981,71.816 ; 121.981,71.308 122.489,71.308 ; 121.981,71.816 121.981,72.324 ; 121.981,71.816 122.489,71.816 ; 121.981,72.324 121.981,72.832 ; 121.981,72.324 122.489,72.324 ; 121.981,72.832 121.981,73.34 ; 121.981,72.832 122.489,72.832 ; 121.981,73.34 121.981,73.848 ; 121.981,73.34 122.489,73.34 ; 121.981,73.848 121.981,74.356 ; 121.981,73.848 122.489,73.848 ; 121.981,74.356 121.981,74.864 ; 121.981,74.356 122.489,74.356 ; 121.981,74.864 121.981,75.372 ; 121.981,74.864 122.489,74.864 ; 121.981,75.372 121.981,75.88 ; 121.981,75.372 122.489,75.372 ; 121.981,75.88 122.489,75.88 ; 121.981,75.88 pad.@121.981,76.388 ; pad.@121.981,76.388 121.981,76.896 ; pad.@121.981,76.388 122.489,76.388 ; 121.981,76.896 121.981,77.404 ; 121.981,76.896 122.489,76.896 ; 121.981,77.404 122.489,77.404 ; 121.981,77.404 121.981,77.912 ; 121.981,77.912 122.489,77.912 ; 121.981,77.912 121.981,78.42 ; 121.981,78.42 122.489,78.42 ; 121.981,78.42 121.981,78.928 ; 121.981,78.928 121.981,79.436 ; 121.981,78.928 122.489,78.928 ; 121.981,79.436 121.981,79.944 ; 121.981,79.436 122.489,79.436 ; 121.981,79.944 121.981,80.198 ; 121.981,79.944 122.489,79.944 ; 121.981,80.198 122.489,80.198 ; 121.981,94.683 pad.@121.981,95.184 ; 121.981,94.683 122.489,94.683 ; pad.@121.981,95.184 pad.@121.981,95.692 ; pad.@121.981,95.184 122.489,95.184 ; pad.@121.981,95.692 121.981,95.946 ; pad.@121.981,95.692 122.489,95.692 ; 121.981,95.946 122.489,95.946 ; 122.094,67.244 ccw(c122.793,67.04) 122.064,67.04 cw(c122.793,67.04) 122.094,67.244 ; 122.094,67.244 cw(c122.793,67.04) 122.278,67.555 ; 122.094,67.244 cw(c122.793,67.04) 122.278,67.555 ; 122.278,67.555 122.475,67.752 ; 122.475,67.752 122.489,67.766 ; 122.489,62.944 122.489,63.18 ; 122.489,62.944 122.997,62.944 ; 122.489,63.18 122.489,63.467 ; 122.489,63.18 122.997,63.18 ; 122.489,63.467 122.743,63.467 ; 122.489,67.766 122.489,68.26 ; 122.489,67.766 122.655,67.932 ; 122.489,68.26 122.489,68.768 ; 122.489,68.26 122.967,68.26 ; 122.489,68.768 122.489,69.276 ; 122.489,68.768 122.997,68.768 ; 122.489,69.276 122.489,69.784 ; 122.489,69.276 122.997,69.276 ; 122.489,69.784 122.489,70.292 ; 122.489,69.784 122.997,69.784 ; 122.489,70.292 pad.@122.489,70.8 ; 122.489,70.292 122.997,70.292 ; pad.@122.489,70.8 122.489,71.308 ; pad.@122.489,70.8 122.997,70.8 ; 122.489,71.308 122.489,71.816 ; 122.489,71.308 122.997,71.308 ; 122.489,71.816 122.489,72.324 ; 122.489,71.816 122.997,71.816 ; 122.489,72.324 122.489,72.832 ; 122.489,72.324 122.997,72.324 ; 122.489,72.832 122.489,73.34 ; 122.489,72.832 122.997,72.832 ; 122.489,73.34 122.489,73.848 ; 122.489,73.34 122.997,73.34 ; 122.489,73.848 122.489,74.356 ; 122.489,73.848 122.997,73.848 ; 122.489,74.356 122.489,74.864 ; 122.489,74.356 122.997,74.356 ; 122.489,74.864 122.489,75.372 ; 122.489,74.864 122.997,74.864 ; 122.489,75.372 122.489,75.88 ; 122.489,75.372 122.997,75.372 ; 122.489,75.88 122.489,76.388 ; 122.489,75.88 122.997,75.88 ; 122.489,76.388 122.489,76.896 ; 122.489,76.388 122.997,76.388 ; 122.489,76.896 122.489,77.404 ; 122.489,76.896 122.997,76.896 ; 122.489,77.404 122.489,77.912 ; 122.489,77.404 122.997,77.404 ; 122.489,77.912 122.489,78.42 ; 122.489,77.912 122.997,77.912 ; 122.489,78.42 122.997,78.42 ; 122.489,78.42 122.489,78.928 ; 122.489,78.928 122.489,79.436 ; 122.489,78.928 122.997,78.928 ; 122.489,79.436 122.489,79.944 ; 122.489,79.436 122.997,79.436 ; 122.489,79.944 122.489,80.198 ; 122.489,79.944 122.997,79.944 ; 122.489,80.198 122.997,80.198 ; 122.489,94.683 122.997,94.683 ; 122.489,94.683 122.489,95.184 ; 122.489,95.184 122.997,95.184 ; 122.489,95.184 122.489,95.692 ; 122.489,95.692 122.997,95.692 ; 122.489,95.692 122.489,95.946 ; 122.489,95.946 122.997,95.946 ; 122.655,67.932 cw(c123.251,67.513) 122.736,68.029 ; 122.655,67.932 cw(c123.251,67.513) 122.736,68.029 ; 122.736,68.029 122.967,68.26 ; 122.743,63.467 ccw(c122.743,64.196) 122.992,63.511 ; 122.743,63.467 ccw(c122.743,64.196) 122.992,63.511 ; 122.967,68.26 122.997,68.29 ; 122.992,63.511 ccw(c122.743,64.196) 122.997,63.513 ; 122.992,63.511 ccw(c122.743,64.196) 122.997,63.513 ; 122.997,62.944 122.997,63.18 ; 122.997,62.944 123.505,62.944 ; 122.997,63.18 123.505,63.18 ; 122.997,63.18 122.997,63.513 ; 122.997,63.513 ccw(c122.743,64.196) 123.258,63.681 ; 122.997,63.513 ccw(c122.743,64.196) 123.258,63.681 ; 122.997,68.29 122.997,68.768 ; 122.997,68.29 123.451,68.744 ; 122.997,68.768 122.997,69.276 ; 122.997,68.768 123.476,68.768 ; 122.997,69.276 122.997,69.784 ; 122.997,69.276 123.505,69.276 ; 122.997,69.784 122.997,70.292 ; 122.997,69.784 123.505,69.784 ; 122.997,70.292 122.997,70.8 ; 122.997,70.292 123.505,70.292 ; 122.997,70.8 123.505,70.8 ; 122.997,70.8 122.997,71.308 ; 122.997,71.308 122.997,71.816 ; 122.997,71.308 123.505,71.308 ; 122.997,71.816 122.997,72.324 ; 122.997,71.816 123.505,71.816 ; 122.997,72.324 122.997,72.832 ; 122.997,72.324 123.505,72.324 ; 122.997,72.832 122.997,73.34 ; 122.997,72.832 123.505,72.832 ; 122.997,73.34 122.997,73.848 ; 122.997,73.34 123.505,73.34 ; 122.997,73.848 122.997,74.356 ; 122.997,73.848 123.505,73.848 ; 122.997,74.356 122.997,74.864 ; 122.997,74.356 123.505,74.356 ; 122.997,74.864 122.997,75.372 ; 122.997,74.864 123.505,74.864 ; 122.997,75.372 122.997,75.88 ; 122.997,75.372 123.505,75.372 ; 122.997,75.88 122.997,76.388 ; 122.997,75.88 123.505,75.88 ; 122.997,76.388 122.997,76.896 ; 122.997,76.388 123.505,76.388 ; 122.997,76.896 122.997,77.404 ; 122.997,76.896 123.505,76.896 ; 122.997,77.404 122.997,77.912 ; 122.997,77.404 123.505,77.404 ; 122.997,77.912 122.997,78.42 ; 122.997,77.912 123.505,77.912 ; 122.997,78.42 123.505,78.42 ; 122.997,78.42 122.997,78.928 ; 122.997,78.928 122.997,79.436 ; 122.997,78.928 123.505,78.928 ; 122.997,79.436 122.997,79.944 ; 122.997,79.436 123.505,79.436 ; 122.997,79.944 122.997,80.198 ; 122.997,79.944 123.505,79.944 ; 122.997,80.198 123.505,80.198 ; 122.997,94.683 122.997,95.184 ; 122.997,94.683 123.084,94.683 ; 122.997,95.184 122.997,95.692 ; 122.997,95.184 123.505,95.184 ; 122.997,95.692 pad.@123.505,95.692 ; 122.997,95.692 122.997,95.946 ; 122.997,95.946 123.505,95.946 ; 123.084,94.683 cw(c123.084,93.954) 123.182,94.676 ; 123.084,94.683 cw(c123.084,93.954) 123.182,94.676 ; 123.091,89.088 123.505,89.088 ; 123.091,89.088 123.091,89.596 ; 123.091,89.088 123.091,88.755 123.265,88.58 ; 123.091,89.596 123.505,89.596 ; 123.091,89.596 123.091,90.088 ccw(c122.408,90.795) 123.107,90.104 ; 123.107,90.104 ccw(c122.408,90.795) 123.373,90.612 ; 123.107,90.104 123.505,90.104 ; 123.182,94.676 cw(c123.084,93.954) 123.505,94.549 ; 123.182,94.676 cw(c123.084,93.954) 123.505,94.549 ; 123.182,94.676 123.505,94.676 ; 123.258,63.681 123.265,63.688 ; 123.265,63.688 123.505,63.928 ; 123.265,63.688 123.505,63.688 ; 123.265,88.58 123.505,88.34 ; 123.265,88.58 123.505,88.58 ; 123.373,90.612 123.505,90.612 ; 123.451,68.744 cw(c123.966,68.228) 123.476,68.768 ; 123.451,68.744 cw(c123.966,68.228) 123.476,68.768 ; 123.476,68.768 cw(c123.966,68.228) 123.505,68.793 ; 123.476,68.768 cw(c123.966,68.228) 123.505,68.793 ; 123.505,62.944 123.505,63.18 ; 123.505,62.944 123.866,62.944 124.013,63.091 ; 123.505,63.18 124.013,63.18 ; 123.505,63.18 123.505,63.688 ; 123.505,63.688 124.013,63.688 ; 123.505,63.688 123.505,63.928 ; 123.505,63.928 123.773,64.196 ; 123.505,68.793 cw(c123.966,68.228) 123.966,68.957 ; 123.505,68.793 cw(c123.966,68.228) 123.966,68.957 ; 123.505,68.793 123.505,69.276 ; 123.505,69.276 123.505,69.784 ; 123.505,69.276 124.013,69.276 ; 123.505,69.784 123.505,70.292 ; 123.505,69.784 124.013,69.784 ; 123.505,70.292 123.505,70.8 ; 123.505,70.292 124.013,70.292 ; 123.505,70.8 123.505,71.308 ; 123.505,70.8 124.013,70.8 ; 123.505,71.308 123.505,71.816 ; 123.505,71.308 124.013,71.308 ; 123.505,71.816 123.505,72.324 ; 123.505,71.816 124.013,71.816 ; 123.505,72.324 123.505,72.832 ; 123.505,72.324 124.013,72.324 ; 123.505,72.832 123.505,73.34 ; 123.505,72.832 124.013,72.832 ; 123.505,73.34 123.505,73.848 ; 123.505,73.34 124.013,73.34 ; 123.505,73.848 123.505,74.356 ; 123.505,73.848 124.013,73.848 ; 123.505,74.356 123.505,74.864 ; 123.505,74.356 124.013,74.356 ; 123.505,74.864 123.505,75.372 ; 123.505,74.864 124.013,74.864 ; 123.505,75.372 123.505,75.88 ; 123.505,75.372 124.013,75.372 ; 123.505,75.88 123.505,76.388 ; 123.505,75.88 124.013,75.88 ; 123.505,76.388 123.505,76.896 ; 123.505,76.388 124.013,76.388 ; 123.505,76.896 123.505,77.404 ; 123.505,76.896 124.013,76.896 ; 123.505,77.404 123.505,77.912 ; 123.505,77.404 124.013,77.404 ; 123.505,77.912 123.505,78.42 ; 123.505,77.912 124.013,77.912 ; 123.505,78.42 124.013,78.42 ; 123.505,78.42 123.505,78.928 ; 123.505,78.928 123.505,79.436 ; 123.505,78.928 124.013,78.928 ; 123.505,79.436 123.505,79.944 ; 123.505,79.436 124.013,79.436 ; 123.505,79.944 123.505,80.198 ; 123.505,79.944 124.013,79.944 ; 123.505,80.198 124.013,80.198 ; 123.505,88.34 123.912,87.934 124.013,87.934 ; 123.505,88.34 123.505,88.58 ; 123.505,88.58 123.505,89.088 ; 123.505,88.58 124.013,88.58 ; 123.505,89.088 123.505,89.596 ; 123.505,89.088 124.013,89.088 ; 123.505,89.596 123.505,90.104 ; 123.505,89.596 124.013,89.596 ; 123.505,90.104 123.505,90.612 ; 123.505,90.104 124.013,90.104 ; 123.505,90.612 124.013,90.612 ; 123.505,90.612 123.505,90.801 ; 123.505,90.801 123.824,91.12 ; 123.505,94.549 cw(c123.084,93.954) 123.599,94.469 ; 123.505,94.549 cw(c123.084,93.954) 123.599,94.469 ; 123.505,94.549 123.505,94.676 ; 123.505,94.676 123.505,95.184 ; 123.505,94.676 124.013,94.676 ; 123.505,95.184 124.013,95.184 ; 123.505,95.184 pad.@123.505,95.692 ; pad.@123.505,95.692 123.505,95.946 ; pad.@123.505,95.692 pad.@124.013,95.692 ; 123.505,95.946 124.013,95.946 ; 123.599,94.469 124.02,94.048 ; 123.773,64.196 124.013,64.436 ; 123.773,64.196 124.013,64.196 ; 123.824,91.12 124.013,91.309 ; 123.824,91.12 124.013,91.12 ; 123.966,68.957 124.013,68.957 ; 124.013,63.091 124.013,63.18 ; 124.013,63.091 124.102,63.18 ; 124.013,63.18 124.013,63.688 ; 124.013,63.18 124.102,63.18 ; 124.013,63.688 124.521,63.688 ; 124.013,63.688 124.013,64.196 ; 124.013,64.196 124.013,64.436 ; 124.013,64.196 124.521,64.196 ; 124.013,64.436 124.281,64.704 ; 124.013,68.957 124.013,69.276 ; 124.013,69.276 124.013,69.784 ; 124.013,69.276 124.521,69.276 ; 124.013,69.784 124.013,70.292 ; 124.013,69.784 124.521,69.784 ; 124.013,70.292 124.013,70.8 ; 124.013,70.292 124.521,70.292 ; 124.013,70.8 124.013,71.308 ; 124.013,70.8 124.521,70.8 ; 124.013,71.308 124.013,71.816 ; 124.013,71.308 124.521,71.308 ; 124.013,71.816 124.013,72.324 ; 124.013,71.816 124.521,71.816 ; 124.013,72.324 124.013,72.832 ; 124.013,72.324 124.521,72.324 ; 124.013,72.832 124.013,73.34 ; 124.013,72.832 124.521,72.832 ; 124.013,73.34 124.013,73.848 ; 124.013,73.34 124.521,73.34 ; 124.013,73.848 124.013,74.356 ; 124.013,73.848 124.521,73.848 ; 124.013,74.356 124.013,74.864 ; 124.013,74.356 124.521,74.356 ; 124.013,74.864 124.013,75.372 ; 124.013,74.864 124.521,74.864 ; 124.013,75.372 124.013,75.88 ; 124.013,75.372 124.521,75.372 ; 124.013,75.88 124.013,76.388 ; 124.013,75.88 124.521,75.88 ; 124.013,76.388 124.013,76.896 ; 124.013,76.388 124.521,76.388 ; 124.013,76.896 124.013,77.404 ; 124.013,76.896 124.521,76.896 ; 124.013,77.404 124.013,77.912 ; 124.013,77.404 124.521,77.404 ; 124.013,77.912 124.013,78.42 ; 124.013,77.912 124.521,77.912 ; 124.013,78.42 124.013,78.928 ; 124.013,78.42 124.521,78.42 ; 124.013,78.928 124.013,79.436 ; 124.013,78.928 124.521,78.928 ; 124.013,79.436 124.013,79.944 ; 124.013,79.436 124.521,79.436 ; 124.013,79.944 124.013,80.198 ; 124.013,79.944 124.394,79.944 ; 124.013,80.198 124.14,80.198 124.394,79.944 ; 124.013,87.934 124.013,88.072 ; 124.013,87.934 124.521,87.934 ; 124.013,88.072 124.013,88.58 ; 124.013,88.072 124.521,88.072 ; 124.013,88.58 124.013,89.088 ; 124.013,88.58 124.521,88.58 ; 124.013,89.088 124.013,89.596 ; 124.013,89.088 124.521,89.088 ; 124.013,89.596 124.013,90.104 ; 124.013,89.596 pad.@124.521,89.596 ; 124.013,90.104 124.013,90.612 ; 124.013,90.104 pad.@124.521,90.104 ; 124.013,90.612 124.013,91.12 ; 124.013,90.612 124.521,90.612 ; 124.013,91.12 124.013,91.309 ; 124.013,91.12 124.521,91.12 ; 124.013,91.309 124.02,91.316 ; 124.013,94.168 124.013,94.676 ; 124.013,94.168 124.521,94.168 ; 124.013,94.676 124.521,94.676 ; 124.013,94.676 124.013,95.184 ; 124.013,95.184 124.521,95.184 ; 124.013,95.184 pad.@124.013,95.692 ; pad.@124.013,95.692 124.521,95.692 ; pad.@124.013,95.692 124.013,95.946 ; 124.013,95.946 124.521,95.946 ; 124.02,91.316 ccw(c123.505,91.831) 124.205,91.628 ; 124.02,91.316 ccw(c123.505,91.831) 124.205,91.628 ; 124.02,94.048 cw(c123.505,93.533) 124.222,93.66 ; 124.02,94.048 cw(c123.505,93.533) 124.222,93.66 ; 124.102,63.18 124.521,63.599 ; 124.205,91.628 ccw(c123.505,91.831) 124.205,91.63 ; 124.205,91.628 ccw(c123.505,91.831) 124.205,91.63 ; 124.205,91.628 124.521,91.628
